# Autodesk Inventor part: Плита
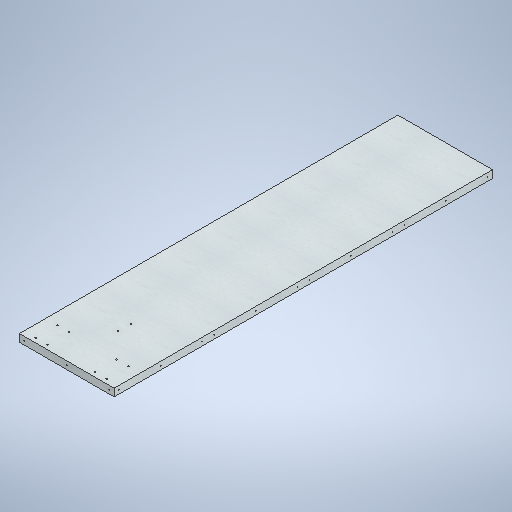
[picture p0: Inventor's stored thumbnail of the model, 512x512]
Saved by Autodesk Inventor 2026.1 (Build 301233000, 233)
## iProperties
Created: 2025-11
Part Number: Плита
Material: Типовые
Document SubType Name: Modeling
Designer: Yury Melnikov
Density: 1 g/cm^3
Appearance: Дерево — окрашенное — белое
Author: Yury Melnikov
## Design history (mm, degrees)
sketch "Эскиз1"
  geometry: L1 (0, 0)-(200, 0); L2 (200, 0)-(200, -16); L3 (200, -16)-(0, -16); L4 (0, -16)-(0, 0); 1 further point
  constraints: 8 end point, 2 parallel, 1 coincident, 1 horizontal, 1 perpendicular
  dimensions: "d0" = 200 distance of L2.end L3.end; "d1" = 16 distance of L1.end L2.end
extrude "Выдавливание1" new body sketch "Эскиз1" distance "d2" = 800; taper "d3" = 0 deg
sketch "Эскиз2"
  geometry: 1 further point
sketch "Эскиз3"
  geometry: L1 (802.124, 0)-(601.062, 0); L2 (601.062, 0)-(601.062, -16); L3 (601.062, -16)-(802.124, -16); L4 (802.124, -16)-(802.124, 0); L5 (601.062, 0)-(400, 0); L6 (400, 0)-(400, -16); L7 (400, -16)-(601.062, -16); L8 (601.062, -16)-(601.062, 0); L9 (400, 0)-(198.938, 0); L10 (198.938, 0)-(198.938, -16); L11 (198.938, -16)-(400, -16); L12 (400, -16)-(400, 0); L13 (198.938, 0)-(-2.124, 0); L14 (-2.124, 0)-(-2.124, -16); L15 (-2.124, -16)-(198.938, -16); L16 (198.938, -16)-(198.938, 0); L17 (800, 0)-(0, 0) reference; C1 r 1 at (789.558, -8); C2 r 1 at (701.613, -8); C3 r 1 at (613.668, -8); C4 r 1 at (588.496, -8); C5 r 1 at (500.551, -8); C6 r 1 at (412.606, -8); C7 r 1 at (387.434, -8); C8 r 1 at (299.489, -8); C9 r 1 at (211.544, -8); C10 r 1 at (186.372, -8); C11 r 1 at (98.427, -8); C12 r 1 at (10.482, -8); 5 further points
  constraints: 32 end point, 12 centre point, 3 horizontal, 2 midpoint, 2 parallel, 1 coincident, 1 collinear, 1 horizontal alignment, 1 perpendicular, 48 other
  dimensions: "d4" = 16 distance of L3.end L1.start; "d5" = 201.062 distance of L1.start L1.end; "d6" = 12.566 distance from line of L4 C1.centre; "d8" = 2 diameter of C1; "d11" = 87.945 distance of C1.centre C2.centre; "d18" = 201.062 distance of L1.start L5.start
extrude "Выдавливание2" cut sketch "Эскиз3" distance "d23" = 10; taper "d24" = 0 deg
node "РабПлоскость1"
mirror "Зеркальное отражение1"
sketch "Эскиз4"
  geometry: L1 (0, -16)-(200, -16) reference; L2 (200, -16)-(200, 0) reference; L3 (200, 0)-(0, 0) reference; L4 (0, 0)-(0, -16) reference; C1 r 1.5 at (10, -8); C2 r 1.5 at (100, -8); C3 r 1.5 at (190, -8); 2 further points
  constraints: 3 centre point, 1 horizontal, 1 horizontal alignment, 1 midpoint, 4 other
  dimensions: "d25" = 3 diameter of C1; "d26" = 10 distance from line of L4 C1.centre; "d29" = 90 distance of C1.centre C2.centre (derived); "d34" = 10 distance from line of L2 C3.centre
extrude "Выдавливание3" cut sketch "Эскиз4" distance "d35" = 100; taper "d36" = 0 deg
sketch "Эскиз5"
  geometry: L1 (25, -745)-(50, -745); L2 (50, -745)-(50, -791); L3 (50, -791)-(25, -791); L4 (25, -791)-(25, -745); L5 (200, -800)-(0, -800) reference; L6 (0, 0)-(0, -800) reference; L7 (100, -800)-(100, -756.623); L8 (175, -745)-(150, -745); L9 (150, -745)-(150, -791); L10 (150, -791)-(175, -791); L11 (175, -791)-(175, -745); C1 r 1.5 at (25, -745); C2 r 1.5 at (50, -745); C3 r 1.5 at (25, -791); C4 r 1.5 at (50, -791); C5 r 1.5 at (175, -745); C6 r 1.5 at (150, -745); C7 r 1.5 at (175, -791); C8 r 1.5 at (150, -791)
  constraints: 18 end point, 8 centre point, 8 symmetric about line, 2 coincident, 2 horizontal, 2 parallel, 2 vertical, 1 midpoint, 1 perpendicular, 10 other
  dimensions: "d37" = 46 distance of L1.end L2.end; "d38" = 25 distance of L1.start L1.end; "d39" = 3 diameter of C1; "d42" = 25 distance of C1.centre C2.centre; "d45" = 46 distance of C1.centre C3.centre; "d48" = 9 distance between parallel lines of L5 L3; "d49" = 25 distance between parallel lines of L4 L6
extrude "Выдавливание4" cut sketch "Эскиз5" distance "d50" = 15; taper "d51" = 0 deg
sketch "Эскиз6"
  geometry: L1 (200, -800)-(0, -800) reference; C1 r 1.5 at (100, -691.569); C2 r 1.5 at (100, -665); 2 further points
  constraints: 2 centre point, 2 vertical alignment, 1 equal radius, 1 midpoint
  dimensions: "d52" = 3 diameter of C1; "d53" = 135 distance from line of L1 C2.centre; "d54" = 26.569 distance of C1.centre C2.centre
extrude "Выдавливание5" cut sketch "Эскиз6" distance "d55" = 15; taper "d56" = 0 deg
node "Твердое тело1"
node "Эскиз — прямоугольный массив1" dims "d11" = 87.945, "d14" = 10
node "Эскиз — прямоугольный массив2" dims "d18" = 201.062, "d21" = 10
node "Спроецированная петля1"
node "Эскиз — прямоугольный массив3" dims "d29" = 90 (derived), "d32" = 10
node "Эскиз — прямоугольный массив4" dims "d42" = 25, "d45" = 46
